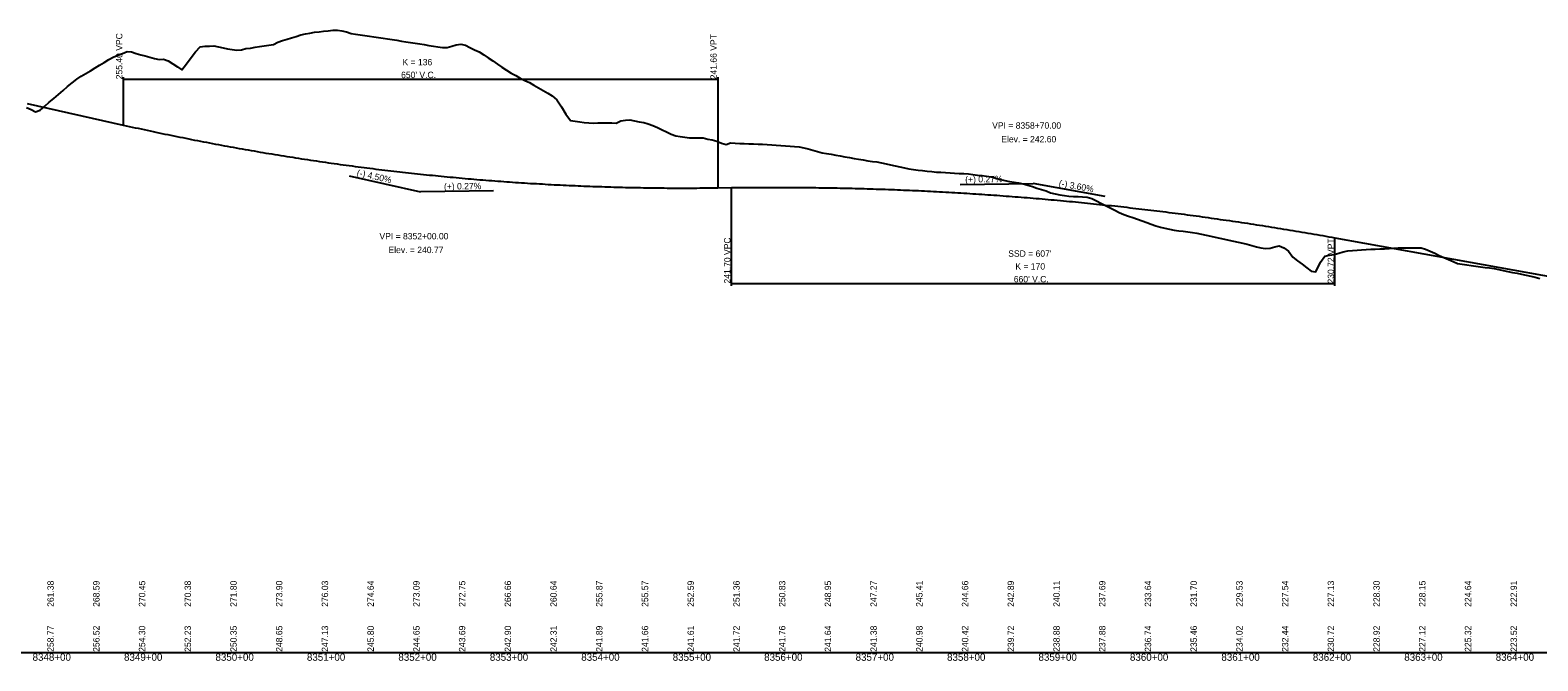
# Model space of a CAD drawing. Extents: x 1838386 to 1955906, y 719739 to 834437.
# Drawn here: x 1879005 to 1880653, y 758480 to 759170 of the extents above; entities that cross this region are included whole.
import ezdxf

# ---------------------------------------------------------------- set-up
doc = ezdxf.new("R2010")
doc.units = 0
for name, color, linetype in [('RD_DDB_GradeTX', 7, 'Continuous'), ('RD_DDB_Profile_EX', 7, 'Continuous'), ('RD_DDB_Profile_Lbl', 7, 'Continuous'), ('RD_DDB_Profile_PR', 7, 'Continuous'), ('RD_DDB_StaTX', 7, 'Continuous'), ('RD_DDB_StripGrade', 7, 'Continuous'), ('RD_DDB_VCLbl', 7, 'Continuous'), ('RD_GPK_Profile_Cell', 7, 'Continuous')]:
    doc.layers.add(name, color=color, linetype=linetype)

msp = doc.modelspace()

# ---------------------------------------------------------------- linework, layer by layer
at = {"layer": 'RD_DDB_GradeTX'}
for p, q in [((1879353.6, 759010.6), (1879431.6, 758993)), ((1880021.6, 759001), (1880101.6, 759002.1)), ((1880180.4, 758988), (1880101.6, 759002.1)), ((1879511.6, 758994.1), (1879431.6, 758993))]:
    msp.add_line(p, q, dxfattribs=at)
at = {"layer": 'RD_DDB_Profile_EX'}
for points in [[(1879200.7, 759152.5), (1879205.7, 759152.6), (1879210.7, 759151.6), (1879215.7, 759150.6), (1879220.7, 759149.6), (1879225.7, 759148.6), (1879230.7, 759148.1), (1879235.7, 759148.4), (1879240.7, 759149.8), (1879245.7, 759150.2), (1879250.7, 759151.1), (1879255.7, 759151.9), (1879260.7, 759152.7), (1879265.7, 759153.5), (1879270.7, 759154.3), (1879275.7, 759156.8), (1879280.7, 759158.4), (1879285.7, 759160), (1879290.7, 759161.5), (1879295.7, 759163.1), (1879300.7, 759164.7), (1879305.7, 759165.7), (1879310.7, 759166.6), (1879315.7, 759167.5), (1879320.7, 759168.1), (1879325.7, 759168.7), (1879330.7, 759169.2), (1879335.7, 759169.7), (1879340.7, 759169.9), (1879345.7, 759169), (1879350.7, 759168.1), (1879355.7, 759166.1), (1879360.7, 759165.4), (1879365.7, 759164.7), (1879370.7, 759163.9), (1879375.7, 759163.2), (1879380.7, 759162.5), (1879385.7, 759161.7), (1879390.7, 759161), (1879395.7, 759160.3), (1879400.7, 759159.5), (1879405.7, 759158.8), (1879410.7, 759158), (1879415.7, 759157.2), (1879420.7, 759156.4), (1879425.7, 759155.6), (1879430.7, 759154.8), (1879435.7, 759154), (1879440.7, 759153.2), (1879445.7, 759152.4), (1879450.7, 759151.7), (1879455.7, 759150.9), (1879460.7, 759150.8), (1879465.7, 759152.3), (1879470.7, 759153.9), (1879475.7, 759154.5), (1879480.7, 759153.4), (1879485.7, 759150.9), (1879490.7, 759148.5), (1879495.7, 759146), (1879500.7, 759143), (1879505.7, 759139.6), (1879510.7, 759136.2), (1879515.7, 759132.8), (1879520.7, 759129.4), (1879525.7, 759126), (1879530.7, 759123), (1879535.7, 759120.1), (1879540.7, 759117.3), (1879545.7, 759114.9), (1879550.7, 759112.5), (1879555.7, 759109.7), (1879560.7, 759106.7), (1879565.7, 759103.8), (1879570.7, 759100.8), (1879575.7, 759097.9), (1879580.7, 759093.8), (1879585.7, 759085.9), (1879590.7, 759078.1), (1879595.7, 759071), (1879600.7, 759070.3), (1879605.7, 759069.6), (1879610.7, 759068.9), (1879615.7, 759068.6), (1879620.7, 759068.3), (1879625.7, 759068.4), (1879630.7, 759068.5), (1879635.7, 759068.5), (1879640.7, 759068.4), (1879645.7, 759068.2), (1879650.7, 759070.7), (1879655.7, 759071.3), (1879660.7, 759071.8), (1879665.7, 759070.7), (1879670.7, 759069.7), (1879675.7, 759068.8), (1879680.7, 759067.4), (1879685.7, 759065.4), (1879690.7, 759063.3), (1879695.7, 759060.9), (1879700.7, 759058.5)], [(1879000.7, 759085.2), (1879005.7, 759082.9), (1879010.7, 759080.7), (1879015.7, 759082.4), (1879020.7, 759086.7), (1879025.7, 759091), (1879030.7, 759095.2), (1879035.7, 759099.5), (1879040.7, 759103.8), (1879045.7, 759108.1), (1879050.7, 759112.4), (1879055.7, 759116.4), (1879060.7, 759119.4), (1879065.7, 759122.4), (1879070.7, 759125.5), (1879075.7, 759128.5), (1879080.7, 759131.5), (1879085.7, 759134.6), (1879090.7, 759137.6), (1879095.7, 759140.5), (1879100.7, 759142.4), (1879105.7, 759144.5), (1879110.7, 759146.5), (1879115.7, 759146.2), (1879120.7, 759144.3), (1879125.7, 759143), (1879130.7, 759141.7), (1879135.7, 759140.2), (1879140.7, 759138.8), (1879145.7, 759137.6), (1879150.7, 759138.2), (1879155.7, 759136.2), (1879160.7, 759132.9), (1879165.7, 759129.6), (1879170.7, 759126.3), (1879175.7, 759133.1), (1879180.7, 759139.9), (1879185.7, 759146.1), (1879190.7, 759151.7), (1879195.7, 759152.2), (1879200.7, 759152.5)], [(1879700.7, 759058.5), (1879705.7, 759056.1), (1879710.7, 759054.1), (1879715.7, 759053.4), (1879720.7, 759052.7), (1879725.7, 759052), (1879730.7, 759052), (1879735.7, 759052.2), (1879740.7, 759052), (1879745.7, 759050.8), (1879750.7, 759049.8), (1879755.7, 759048.6), (1879760.7, 759046.3), (1879765.7, 759044.8), (1879770.7, 759046.6), (1879775.7, 759046.2), (1879780.7, 759046), (1879785.7, 759045.8), (1879790.7, 759045.6), (1879795.7, 759045.4), (1879800.7, 759045.3), (1879805.7, 759045.1), (1879810.7, 759044.9), (1879815.7, 759044.6), (1879820.7, 759044.2), (1879825.7, 759043.8), (1879830.7, 759043.4), (1879835.7, 759043), (1879840.7, 759042.5), (1879845.7, 759042.1), (1879850.7, 759041.3), (1879855.7, 759039.9), (1879860.7, 759038.5), (1879865.7, 759037.2), (1879870.7, 759035.8), (1879875.7, 759034.9), (1879880.7, 759034.1), (1879885.7, 759033.2), (1879890.7, 759032.4), (1879895.7, 759031.3), (1879900.7, 759030.4), (1879905.7, 759029.6), (1879910.7, 759028.8), (1879915.7, 759028), (1879920.7, 759027.1), (1879925.7, 759026.3), (1879930.7, 759025.7), (1879935.7, 759024.6), (1879940.7, 759023.6), (1879945.7, 759022.5), (1879950.7, 759021.4), (1879955.7, 759020.4), (1879960.7, 759019.4), (1879965.7, 759018.3), (1879970.7, 759017.4), (1879975.7, 759016.9), (1879980.7, 759016.3), (1879985.7, 759015.7), (1879990.7, 759015.2), (1879995.7, 759014.7), (1880000.7, 759014.5), (1880005.7, 759014.2), (1880010.7, 759013.9), (1880015.7, 759013.5), (1880020.7, 759013.2), (1880025.7, 759013), (1880030.7, 759012.6), (1880035.7, 759012), (1880040.7, 759011.4), (1880045.7, 759010.9), (1880050.7, 759010.2), (1880055.7, 759009.4), (1880060.7, 759008), (1880065.7, 759006.6), (1880070.7, 759005.5), (1880075.7, 759004.5), (1880080.7, 759003.7), (1880085.7, 759002.9), (1880090.7, 759001.6), (1880095.7, 759000.3), (1880100.7, 758998.8), (1880105.7, 758997.2), (1880110.7, 758995.6), (1880115.7, 758994), (1880120.7, 758992), (1880125.7, 758990.9), (1880130.7, 758989.9), (1880135.7, 758988.9), (1880140.7, 758988.4), (1880145.7, 758988.1), (1880150.7, 758987.9), (1880155.7, 758987.6), (1880160.7, 758987.1), (1880165.7, 758985.6), (1880170.7, 758983.1), (1880175.7, 758980.6), (1880180.7, 758978.1), (1880185.7, 758975.6), (1880190.7, 758973.1), (1880195.7, 758970.6), (1880200.7, 758968.1)], [(1880200.7, 758968.1), (1880205.7, 758966.4), (1880210.7, 758964.8), (1880215.7, 758963), (1880220.7, 758961.2), (1880225.7, 758959.4), (1880230.7, 758957.7), (1880235.7, 758955.9), (1880240.7, 758954.3), (1880245.7, 758953.2), (1880250.7, 758952.2), (1880255.7, 758951.2), (1880260.7, 758950.4), (1880265.7, 758949.9), (1880270.7, 758949.3), (1880275.7, 758948.6), (1880280.7, 758947.8), (1880285.7, 758946.9), (1880290.7, 758945.8), (1880295.7, 758944.6), (1880300.7, 758943.5), (1880305.7, 758942.4), (1880310.7, 758941.4), (1880315.7, 758940), (1880320.7, 758939.1), (1880325.7, 758938.1), (1880330.7, 758937), (1880335.7, 758935.8), (1880340.7, 758934.4), (1880345.7, 758933), (1880350.7, 758931.7), (1880355.7, 758930.9), (1880360.7, 758931.4), (1880365.7, 758932.9), (1880370.7, 758933.8), (1880375.7, 758931.6), (1880380.7, 758928), (1880385.7, 758921.6), (1880390.7, 758917.7), (1880395.7, 758913.8), (1880400.7, 758909.9), (1880405.7, 758906.1), (1880410.7, 758905.6), (1880415.7, 758916), (1880420.7, 758922.7), (1880425.7, 758923.6), (1880430.7, 758924.5), (1880435.7, 758926), (1880440.7, 758927.3), (1880445.7, 758928.4), (1880450.7, 758929), (1880455.7, 758929.3), (1880460.7, 758929.7), (1880465.7, 758930), (1880470.7, 758930.2), (1880475.7, 758930.3), (1880480.7, 758930.6), (1880485.7, 758930.8), (1880490.7, 758931.1), (1880495.7, 758931.3), (1880500.7, 758931.6), (1880505.7, 758931.6), (1880510.7, 758931.7), (1880515.7, 758931.8), (1880520.7, 758931.9), (1880525.7, 758931.9), (1880530.7, 758930.3), (1880535.7, 758928.1), (1880540.7, 758925.8), (1880545.7, 758923.5), (1880550.7, 758921.2), (1880555.7, 758919), (1880560.7, 758916.7), (1880565.7, 758914.6), (1880570.7, 758913.9), (1880575.7, 758913.2), (1880580.7, 758912.5), (1880585.7, 758911.8), (1880590.7, 758911.1), (1880595.7, 758910.4), (1880600.7, 758909.8), (1880605.7, 758909.1), (1880610.7, 758908.1), (1880615.7, 758907), (1880620.7, 758906), (1880625.7, 758904.9), (1880630.7, 758903.9), (1880635.7, 758902.8), (1880640.7, 758901.7), (1880645.7, 758900.7), (1880650.7, 758899.8), (1880655.7, 758898.1)]]:
    msp.add_lwpolyline(points, dxfattribs=at)
at = {"layer": 'RD_DDB_Profile_PR'}
for p, q in [((1879001.6, 759089.8), (1879106.6, 759066.1)), ((1879756.6, 758997.4), (1879771.6, 758997.6)), ((1880431.6, 758942.7), (1880941.6, 758850.9))]:
    msp.add_line(p, q, dxfattribs=at)
for points in [[(1879106.6, 759066.1), (1879119.6, 759063.2), (1879132.6, 759060.4), (1879145.6, 759057.6), (1879158.6, 759054.9), (1879171.6, 759052.3), (1879184.6, 759049.7), (1879197.6, 759047.2), (1879210.6, 759044.7), (1879223.6, 759042.3), (1879236.6, 759040), (1879249.6, 759037.7), (1879262.6, 759035.5), (1879275.6, 759033.4), (1879288.6, 759031.3), (1879301.6, 759029.2), (1879314.6, 759027.3), (1879327.6, 759025.4), (1879340.6, 759023.5), (1879353.6, 759021.8), (1879366.6, 759020), (1879379.6, 759018.4), (1879392.6, 759016.8), (1879405.6, 759015.3), (1879418.6, 759013.8), (1879431.6, 759012.4), (1879444.6, 759011.1), (1879457.6, 759009.8), (1879470.6, 759008.6), (1879483.6, 759007.4), (1879496.6, 759006.3), (1879509.6, 759005.3), (1879522.6, 759004.3), (1879535.6, 759003.4), (1879548.6, 759002.5), (1879561.6, 759001.8), (1879574.6, 759001), (1879587.6, 759000.4), (1879600.6, 758999.8), (1879613.6, 758999.2), (1879626.6, 758998.8), (1879639.6, 758998.4), (1879652.6, 758998), (1879665.6, 758997.7), (1879678.6, 758997.5), (1879691.6, 758997.3), (1879704.6, 758997.2), (1879717.6, 758997.2), (1879730.6, 758997.2), (1879743.6, 758997.3), (1879756.6, 758997.4)], [(1879771.6, 758997.6), (1879784.8, 758997.8), (1879798, 758997.9), (1879811.2, 758997.9), (1879824.4, 758997.9), (1879837.6, 758997.9), (1879850.8, 758997.8), (1879864, 758997.6), (1879877.2, 758997.4), (1879890.4, 758997.2), (1879903.6, 758996.9), (1879916.8, 758996.5), (1879930, 758996.1), (1879943.2, 758995.7), (1879956.4, 758995.1), (1879969.6, 758994.6), (1879982.8, 758994), (1879996, 758993.3), (1880009.2, 758992.6), (1880022.4, 758991.8), (1880035.6, 758991), (1880048.8, 758990.1), (1880062, 758989.2), (1880075.2, 758988.2), (1880088.4, 758987.2), (1880101.6, 758986.2), (1880114.8, 758985), (1880128, 758983.9), (1880141.2, 758982.6), (1880154.4, 758981.4), (1880167.6, 758980), (1880180.8, 758978.6), (1880194, 758977.2), (1880207.2, 758975.7), (1880220.4, 758974.2), (1880233.6, 758972.6), (1880246.8, 758971), (1880260, 758969.3), (1880273.2, 758967.6), (1880286.4, 758965.8), (1880299.6, 758963.9), (1880312.8, 758962), (1880326, 758960.1), (1880339.2, 758958.1), (1880352.4, 758956.1), (1880365.6, 758954), (1880378.8, 758951.8), (1880392, 758949.6), (1880405.2, 758947.4), (1880418.4, 758945.1), (1880431.6, 758942.7)]]:
    msp.add_spline(points, degree=3, dxfattribs=at)
at = {"layer": 'RD_DDB_VCLbl'}
for p, q in [((1879106.6, 759118.6), (1879106.6, 759066.1)), ((1879106.6, 759116.1), (1879756.6, 759116.1)), ((1879756.6, 759118.6), (1879756.6, 758997.4)), ((1879771.6, 758890.2), (1879771.6, 758997.6)), ((1880431.6, 758890.2), (1880431.6, 758942.7)), ((1879771.6, 758892.7), (1880431.6, 758892.7))]:
    msp.add_line(p, q, dxfattribs=at)
at = {"layer": 'RD_GPK_Profile_Cell'}
msp.add_line((1877681.6, 758489.1), (1884181.6, 758489.1), dxfattribs=at)

# ---------------------------------------------------------------- texts
at = {"layer": 'RD_DDB_GradeTX'}
for s, rotation, p in [('(-) 4.50%', 347.3196, (1879361.5, 759010.8)), ('(+) 0.27%', 0.7787, (1879457.3, 758995.4)), ('(+) 0.27%', 0.7787, (1880027.3, 759003.1)), ('(-) 3.60%', 349.796, (1880129.2, 758999.2))]:
    msp.add_text(s, height=7, rotation=rotation, dxfattribs=at).set_placement(p)
at = {"layer": 'RD_DDB_Profile_Lbl'}
for s, p in [('VPI = 8358+70.00', (1880056.7, 759062.1)), ('Elev. = 242.60', (1880066.7, 759047.1)), ('VPI = 8352+00.00', (1879386.7, 758941)), ('Elev. = 240.77', (1879396.6, 758926))]:
    msp.add_text(s, height=7, dxfattribs=at).set_placement(p)
at = {"layer": 'RD_DDB_StaTX'}
for s, p in [('8348+00', (1879007.4, 758480.1)), ('8349+00', (1879107.4, 758480.1)), ('8350+00', (1879207.4, 758480.1)), ('8351+00', (1879307.4, 758480.1)), ('8352+00', (1879407.4, 758480.1)), ('8353+00', (1879507.4, 758480.1)), ('8354+00', (1879607.4, 758480.1)), ('8355+00', (1879707.4, 758480.1)), ('8356+00', (1879807.4, 758480.1)), ('8357+00', (1879907.4, 758480.1)), ('8358+00', (1880007.4, 758480.1)), ('8359+00', (1880107.4, 758480.1)), ('8360+00', (1880207.4, 758480.1)), ('8361+00', (1880307.4, 758480.1)), ('8362+00', (1880407.4, 758480.1)), ('8363+00', (1880507.4, 758480.1)), ('8364+00', (1880607.4, 758480.1))]:
    msp.add_text(s, height=8, dxfattribs=at).set_placement(p)
at = {"layer": 'RD_DDB_StripGrade'}
for s, p in [('255.40 VPC', (1879105.6, 759116.1)), ('241.66 VPT', (1879755.6, 759116.1)), ('241.70 VPC', (1879770.6, 758892.7)), ('230.72 VPT', (1880430.6, 758892.7)), ('261.38', (1879030.6, 758539.1)), ('268.59', (1879080.6, 758539.1)), ('270.45', (1879130.6, 758539.1)), ('270.38', (1879180.6, 758539.1)), ('271.80', (1879230.6, 758539.1)), ('273.90', (1879280.6, 758539.1)), ('276.03', (1879330.6, 758539.1)), ('274.64', (1879380.6, 758539.1)), ('273.09', (1879430.6, 758539.1)), ('272.75', (1879480.6, 758539.1)), ('266.66', (1879530.6, 758539.1)), ('260.64', (1879580.6, 758539.1)), ('255.87', (1879630.6, 758539.1)), ('255.57', (1879680.6, 758539.1)), ('252.59', (1879730.6, 758539.1)), ('251.36', (1879780.6, 758539.1)), ('250.83', (1879830.6, 758539.1)), ('248.95', (1879880.6, 758539.1)), ('247.27', (1879930.6, 758539.1)), ('245.41', (1879980.6, 758539.1)), ('244.66', (1880030.6, 758539.1)), ('242.89', (1880080.6, 758539.1)), ('240.11', (1880130.6, 758539.1)), ('237.69', (1880180.6, 758539.1)), ('233.64', (1880230.6, 758539.1)), ('231.70', (1880280.6, 758539.1)), ('229.53', (1880330.6, 758539.1)), ('227.54', (1880380.6, 758539.1)), ('227.13', (1880430.6, 758539.1)), ('228.30', (1880480.6, 758539.1)), ('228.15', (1880530.6, 758539.1)), ('224.64', (1880580.6, 758539.1)), ('222.91', (1880630.6, 758539.1)), ('258.77', (1879030.6, 758489.9)), ('256.52', (1879080.6, 758489.9)), ('254.30', (1879130.6, 758489.9)), ('252.23', (1879180.6, 758489.9)), ('250.35', (1879230.6, 758489.9)), ('248.65', (1879280.6, 758489.9)), ('247.13', (1879330.6, 758489.9)), ('245.80', (1879380.6, 758489.9)), ('244.65', (1879430.6, 758489.9)), ('243.69', (1879480.6, 758489.9)), ('242.90', (1879530.6, 758489.9)), ('242.31', (1879580.6, 758489.9)), ('241.89', (1879630.6, 758489.9)), ('241.66', (1879680.6, 758489.9)), ('241.61', (1879730.6, 758489.9)), ('241.72', (1879780.6, 758489.9)), ('241.76', (1879830.6, 758489.9)), ('241.64', (1879880.6, 758489.9)), ('241.38', (1879930.6, 758489.9)), ('240.98', (1879980.6, 758489.9)), ('240.42', (1880030.6, 758489.9)), ('239.72', (1880080.6, 758489.9)), ('238.88', (1880130.6, 758489.9)), ('237.88', (1880180.6, 758489.9)), ('236.74', (1880230.6, 758489.9)), ('235.46', (1880280.6, 758489.9)), ('234.02', (1880330.6, 758489.9)), ('232.44', (1880380.6, 758489.9)), ('230.72', (1880430.6, 758489.9)), ('228.92', (1880480.6, 758489.9)), ('227.12', (1880530.6, 758489.9)), ('225.32', (1880580.6, 758489.9)), ('223.52', (1880630.6, 758489.9))]:
    msp.add_text(s, height=7, rotation=90, dxfattribs=at).set_placement(p)
at = {"layer": 'RD_DDB_VCLbl'}
for s, p in [('K = 136', (1879411.9, 759131.4)), ("650' V.C.", (1879410.4, 759117.4)), ("SSD = 607'", (1880074.3, 758922)), ('K = 170', (1880082.1, 758908)), ("660' V.C.", (1880080.4, 758894))]:
    msp.add_text(s, height=7, dxfattribs=at).set_placement(p)

doc.saveas('drawing.dxf')
